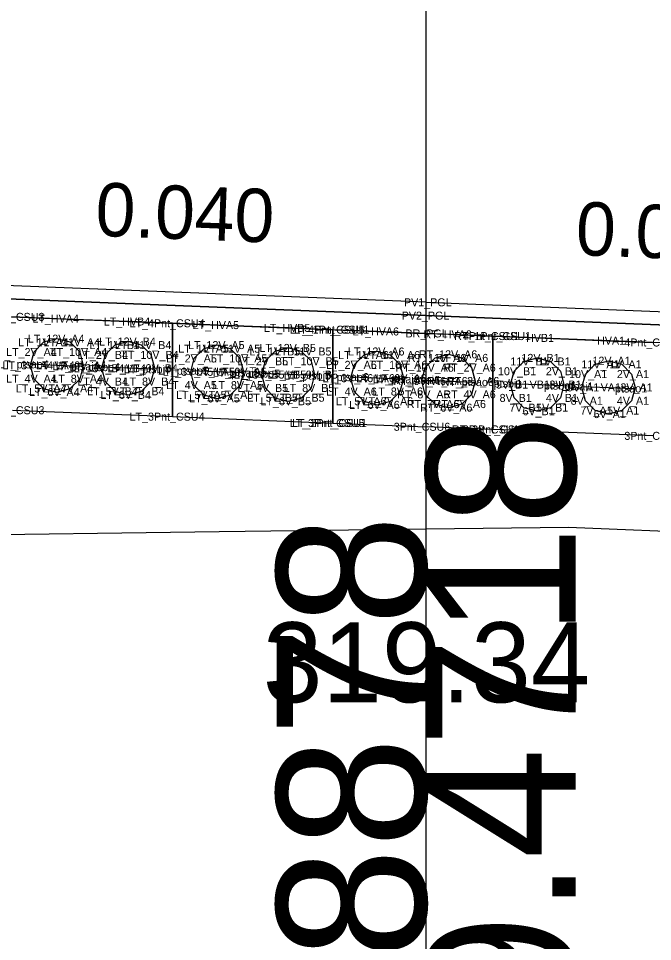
# Model space of a CAD drawing. Extents: x -26 to 1163, y -10 to 9537.
# Drawn here: x 72.36 to 84.24, y 5507.61 to 5524.91 of the extents above; entities that cross this region are included whole.
import ezdxf

# ---------------------------------------------------------------- set-up
doc = ezdxf.new("R2010")
doc.units = 0
for name, color, linetype in [('Exist Cross Section Cell', 7, 'Continuous'), ('Exist XS Center Line Elevation Label', 7, 'Continuous'), ('Exist XS Ground Line', 7, 'Continuous'), ('Prop CMT Concrete Structures', 7, 'Continuous'), ('Prop CMT Corridor Surface Symbology Blue', 7, 'Continuous'), ('Prop CMT Pvmt Course 1', 7, 'Continuous'), ('Prop CMT Pvmt Course 2', 7, 'Continuous'), ('Prop XS SE Text', 7, 'Continuous'), ('Scratch_Level_0', 7, 'Continuous')]:
    doc.layers.add(name, color=color, linetype=linetype)

msp = doc.modelspace()

# ---------------------------------------------------------------- linework, layer by layer
at = {"layer": 'Exist Cross Section Cell'}
msp.add_line((80, 5500), (80, 5546.131), dxfattribs=at)
at = {"layer": 'Exist XS Ground Line'}
msp.add_lwpolyline([(50.408, 5507.818), (57.975, 5511.563), (61.745, 5513.361), (70.287, 5515.157), (70.652, 5515.222), (76.125, 5515.292), (80, 5515.342), (82.665, 5515.377), (85.409, 5515.26), (94.805, 5514.85), (98.043, 5514.258), (104.757, 5511.598), (113.21, 5508.172), (121.817, 5507.493), (125.269, 5507.214), (127.758, 5507.11), (137.804, 5508.533), (143.24, 5508.791), (148.098, 5507.061), (150.039, 5505.923), (155.893, 5501.246), (156.599, 5500.79), (160, 5500.863)], dxfattribs=at)
at = {"layer": 'Prop CMT Concrete Structures'}
for points in [[(75.25, 5519.197), (74.417, 5519.23), (73.083, 5519.283), (72.25, 5519.317)], [(78.25, 5519.077), (77.417, 5519.11), (76.083, 5519.163), (75.25, 5519.197)], [(75.25, 5519.197), (75.25, 5517.447)], [(75.25, 5517.447), (75.25, 5519.197)], [(80, 5519.007), (79.083, 5519.043), (78.25, 5519.077)], [(78.25, 5519.077), (78.25, 5517.327)], [(78.25, 5517.327), (78.25, 5519.077)], [(73.083, 5518.908), (72.833, 5518.841), (72.65, 5518.658), (72.583, 5518.408)], [(73.583, 5518.408), (73.516, 5518.658), (73.333, 5518.841), (73.083, 5518.908)], [(74.417, 5518.855), (74.167, 5518.788), (73.984, 5518.605), (73.917, 5518.355)], [(74.917, 5518.355), (74.85, 5518.605), (74.667, 5518.788), (74.417, 5518.855)], [(80, 5517.257), (80, 5519.007)], [(80, 5519.007), (80.417, 5518.99), (81.25, 5518.957)], [(80, 5517.257), (80, 5519.007)], [(81.25, 5518.957), (81.25, 5517.207)], [(81.25, 5518.957), (82.083, 5518.923), (83.417, 5518.87), (84.25, 5518.837)], [(81.25, 5517.207), (81.25, 5518.957)], [(76.083, 5518.788), (75.833, 5518.721), (75.65, 5518.538), (75.583, 5518.288)], [(76.583, 5518.288), (76.516, 5518.538), (76.333, 5518.721), (76.083, 5518.788)], [(77.417, 5518.735), (77.167, 5518.668), (76.984, 5518.485), (76.917, 5518.235)], [(77.917, 5518.235), (77.85, 5518.485), (77.667, 5518.668), (77.417, 5518.735)], [(79.083, 5518.668), (78.833, 5518.601), (78.65, 5518.418), (78.583, 5518.168)], [(79.583, 5518.168), (79.516, 5518.418), (79.333, 5518.601), (79.083, 5518.668)], [(79.917, 5518.115), (79.984, 5518.365), (80.167, 5518.548), (80.417, 5518.615)], [(80.417, 5518.615), (80.667, 5518.548), (80.85, 5518.365), (80.917, 5518.115)], [(81.583, 5518.048), (81.65, 5518.298), (81.833, 5518.481), (82.083, 5518.548)], [(82.083, 5518.548), (82.333, 5518.481), (82.516, 5518.298), (82.583, 5518.048)], [(82.917, 5517.995), (82.984, 5518.245), (83.167, 5518.428), (83.417, 5518.495)], [(83.417, 5518.495), (83.667, 5518.428), (83.85, 5518.245), (83.917, 5517.995)], [(72.583, 5518.408), (72.65, 5518.158), (72.833, 5517.975), (73.083, 5517.908), (73.333, 5517.975), (73.516, 5518.158), (73.583, 5518.408)], [(73.917, 5518.355), (73.984, 5518.105), (74.167, 5517.922), (74.417, 5517.855), (74.667, 5517.922), (74.85, 5518.105), (74.917, 5518.355)], [(75.583, 5518.288), (75.65, 5518.038), (75.833, 5517.855), (76.083, 5517.788), (76.333, 5517.855), (76.516, 5518.038), (76.583, 5518.288)], [(76.917, 5518.235), (76.984, 5517.985), (77.167, 5517.802), (77.417, 5517.735), (77.667, 5517.802), (77.85, 5517.985), (77.917, 5518.235)], [(78.583, 5518.168), (78.65, 5517.918), (78.833, 5517.735), (79.083, 5517.668), (79.333, 5517.735), (79.516, 5517.918), (79.583, 5518.168)], [(80.917, 5518.115), (80.85, 5517.865), (80.667, 5517.682), (80.417, 5517.615), (80.167, 5517.682), (79.984, 5517.865), (79.917, 5518.115)], [(82.583, 5518.048), (82.516, 5517.798), (82.333, 5517.615), (82.083, 5517.548), (81.833, 5517.615), (81.65, 5517.798), (81.583, 5518.048)], [(83.917, 5517.995), (83.85, 5517.745), (83.667, 5517.562), (83.417, 5517.495), (83.167, 5517.562), (82.984, 5517.745), (82.917, 5517.995)], [(72.25, 5517.567), (75.25, 5517.447)], [(75.25, 5517.447), (78.25, 5517.327)], [(78.25, 5517.327), (80, 5517.257)], [(81.25, 5517.207), (80, 5517.257)], [(84.25, 5517.087), (81.25, 5517.207)]]:
    msp.add_lwpolyline(points, dxfattribs=at)
at = {"layer": 'Prop CMT Corridor Surface Symbology Blue'}
for points in [[(73.573, 5518.389), (73.083, 5518.408), (72.593, 5518.428)], [(74.907, 5518.335), (74.417, 5518.355), (73.927, 5518.375)], [(76.573, 5518.269), (76.083, 5518.288), (75.593, 5518.308)], [(77.907, 5518.215), (77.417, 5518.235), (76.927, 5518.255)], [(79.573, 5518.149), (79.083, 5518.168), (78.593, 5518.188)], [(79.927, 5518.135), (80.417, 5518.115), (80.907, 5518.095)], [(81.593, 5518.068), (82.083, 5518.048), (82.573, 5518.029)], [(82.927, 5518.015), (83.417, 5517.995), (83.907, 5517.975)]]:
    msp.add_lwpolyline(points, dxfattribs=at)
at = {"layer": 'Prop CMT Pvmt Course 1'}
for points in [[(80, 5519.59), (71, 5519.95), (61.5, 5520.33)], [(61.5, 5520.33), (61.5, 5520.08), (80, 5519.34)], [(80, 5519.34), (80, 5519.59)], [(80, 5519.59), (89, 5519.23), (98.376, 5518.855)], [(80, 5519.34), (80, 5519.59)], [(98.376, 5518.855), (98.376, 5518.605), (80, 5519.34)]]:
    msp.add_lwpolyline(points, dxfattribs=at)
at = {"layer": 'Prop CMT Pvmt Course 2'}
for points in [[(80, 5519.34), (61.5, 5520.08)], [(61.5, 5520.08), (61.5, 5519.747), (80, 5519.007)], [(80, 5519.007), (80, 5519.34)], [(80, 5519.34), (98.376, 5518.605)], [(80, 5519.007), (80, 5519.34)], [(98.376, 5518.605), (98.375, 5518.272), (80, 5519.007)]]:
    msp.add_lwpolyline(points, dxfattribs=at)

# ---------------------------------------------------------------- texts
at = {"layer": 'Exist Cross Section Cell'}
for s, p in [('E 2058789.4718', (82.8, 5490)), ('N 688802.8878', (80, 5490))]:
    msp.add_text(s, height=2.8, rotation=90, dxfattribs=at).set_placement(p)
at = {"layer": 'Exist XS Center Line Elevation Label'}
msp.add_text('319.34', height=1.5, dxfattribs=at).set_placement((76.941, 5512.092))
at = {"layer": 'Prop XS SE Text'}
for p in [(73.791, 5520.839), (82.791, 5520.479)]:
    msp.add_text('0.040', height=1, rotation=357.7094, dxfattribs=at).set_placement(p)
at = {"layer": 'Scratch_Level_0'}
for s, p in [('PV1_PGL', (79.585, 5519.515)), ('LT_4Pnt_CSU3', (71.444, 5519.242)), ('LT_HVA4', (72.625, 5519.208)), ('PV2_PGL', (79.543, 5519.265)), ('LT_HVB4', (73.961, 5519.155)), ('LT_4Pnt_CSU4', (74.444, 5519.122)), ('LT_HVA5', (75.625, 5519.088)), ('LT_HVB5', (76.961, 5519.035)), ('LT_4Pnt_CSU5', (77.444, 5519.002)), ('LT_1Pnt_CSU1', (77.53, 5519.002)), ('LT_HVA6', (78.622, 5518.968)), ('BR_PGL', (79.613, 5518.932)), ('RT_HVA6', (79.951, 5518.915)), ('RT_1Pnt_CSU1', (80.526, 5518.882)), ('4Pnt_CSU1', (80.689, 5518.882)), ('LT_1V_A4', (72.356, 5518.766)), ('LT_12V_A4', (72.539, 5518.833)), ('LT_11V_A4', (72.831, 5518.766)), ('LT_1V_B4', (73.692, 5518.713)), ('LT_12V_B4', (73.875, 5518.78)), ('LT_11V_B4', (74.167, 5518.713)), ('LT_12V_A5', (75.539, 5518.713)), ('HVB1', (81.872, 5518.848)), ('HVA1', (83.203, 5518.795)), ('4Pnt_CSU', (83.714, 5518.762)), ('LT_2V_A4', (72.131, 5518.583)), ('LT_10V_A4', (72.966, 5518.583)), ('LT_2V_B4', (73.466, 5518.53)), ('LT_10V_B4', (74.302, 5518.53)), ('LT_1V_A5', (75.356, 5518.646)), ('LT_11V_A5', (75.831, 5518.646)), ('LT_1V_B5', (76.692, 5518.593)), ('LT_12V_B5', (76.875, 5518.66)), ('LT_11V_B5', (77.167, 5518.593)), ('LT_1V_A6', (78.353, 5518.526)), ('LT_12V_A6', (78.535, 5518.593)), ('LT_11V_A6', (78.828, 5518.526)), ('RT_12V_A6', (79.865, 5518.54)), ('LT_ptsao4', (71.982, 5518.353)), ('LT_2V_A5', (75.131, 5518.463)), ('LT_10V_A5', (75.966, 5518.463)), ('LT_2V_B5', (76.466, 5518.41)), ('LT_10V_B5', (77.302, 5518.41)), ('LT_2V_A6', (78.127, 5518.343)), ('LT_10V_A6', (78.962, 5518.343)), ('RT_11V_A6', (79.658, 5518.473)), ('RT_1V_A6', (80.182, 5518.473)), ('11V_B1', (81.578, 5518.406)), ('12V_B1', (81.786, 5518.473)), ('1V_B1', (82.103, 5518.406)), ('11V_A1', (82.909, 5518.353)), ('12V_A1', (83.117, 5518.42)), ('1V_A1', (83.434, 5518.353)), ('LT_3V_A4', (72.064, 5518.333)), ('LT_VA4', (72.692, 5518.333)), ('LT_ptsai4', (73.002, 5518.314)), ('LT_9V_A4', (73.064, 5518.333)), ('LT_ptsbo4', (73.316, 5518.3)), ('LT_3V_B4', (73.399, 5518.28)), ('LT_VB4', (74.028, 5518.28)), ('LT_ptsbi4', (74.336, 5518.26)), ('LT_9V_B4', (74.399, 5518.28)), ('LT_ptsao5', (74.982, 5518.233)), ('LT_3V_A5', (75.064, 5518.213)), ('LT_VA5', (75.692, 5518.213)), ('LT_ptsai5', (76.002, 5518.194)), ('LT_9V_A5', (76.064, 5518.213)), ('LT_ptsbo5', (76.316, 5518.18)), ('RT_10V_A6', (79.426, 5518.29)), ('RT_2V_A6', (80.323, 5518.29)), ('10V_B1', (81.347, 5518.223)), ('2V_B1', (82.244, 5518.223)), ('10V_A1', (82.678, 5518.17)), ('2V_A1', (83.574, 5518.17)), ('LT_4V_A4', (72.131, 5518.083)), ('LT_8V_A4', (72.997, 5518.083)), ('LT_4V_B4', (73.466, 5518.03)), ('LT_8V_B4', (74.332, 5518.03)), ('LT_3V_B5', (76.399, 5518.16)), ('LT_VB5', (77.028, 5518.16)), ('LT_ptsbi5', (77.336, 5518.14)), ('LT_9V_B5', (77.399, 5518.16)), ('LT_ptsao6', (77.978, 5518.113)), ('LT_3V_A6', (78.06, 5518.093)), ('LT_VA6', (78.689, 5518.093)), ('LT_ptsai6', (78.998, 5518.074)), ('LT_9V_A6', (79.06, 5518.093)), ('RT_ptsai6', (79.348, 5518.06)), ('RT_9V_A6', (79.39, 5518.04)), ('RT_VA6', (80.019, 5518.04)), ('RT_ptsao6', (80.288, 5518.02)), ('RT_3V_A6', (80.39, 5518.04)), ('ptsbi1', (81.267, 5517.993)), ('LT_5V_A4', (72.314, 5517.9)), ('LT_6V_A4', (72.56, 5517.833)), ('LT_7V_A4', (72.814, 5517.9)), ('LT_5V_B4', (73.649, 5517.847)), ('LT_7V_B4', (74.149, 5517.847)), ('LT_4V_A5', (75.131, 5517.963)), ('LT_8V_A5', (75.997, 5517.963)), ('LT_4V_B5', (76.466, 5517.91)), ('LT_8V_B5', (77.332, 5517.91)), ('LT_4V_A6', (78.127, 5517.843)), ('LT_8V_A6', (78.993, 5517.843)), ('9V_B1', (81.31, 5517.973)), ('VB1', (81.939, 5517.973)), ('ptsbo1', (82.207, 5517.954)), ('3V_B1', (82.31, 5517.973)), ('ptsai1', (82.6, 5517.94)), ('9V_A1', (82.641, 5517.92)), ('VA1', (83.27, 5517.92)), ('ptsao1', (83.539, 5517.9)), ('3V_A1', (83.641, 5517.92)), ('LT_6V_B4', (73.896, 5517.78)), ('LT_5V_A5', (75.314, 5517.78)), ('LT_6V_A5', (75.56, 5517.713)), ('LT_7V_A5', (75.814, 5517.78)), ('LT_5V_B5', (76.649, 5517.727)), ('LT_6V_B5', (76.896, 5517.66)), ('LT_7V_B5', (77.149, 5517.727)), ('LT_5V_A6', (78.31, 5517.66)), ('LT_7V_A6', (78.81, 5517.66)), ('RT_8V_A6', (79.457, 5517.79)), ('RT_4V_A6', (80.323, 5517.79)), ('8V_B1', (81.377, 5517.723)), ('4V_B1', (82.244, 5517.723)), ('8V_A1', (82.708, 5517.67)), ('4V_A1', (83.574, 5517.67)), ('LT_3Pnt_CSU3', (71.444, 5517.492)), ('LT_6V_A6', (78.557, 5517.593)), ('RT_7V_A6', (79.64, 5517.607)), ('RT_6V_A6', (79.886, 5517.54)), ('RT_5V_A6', (80.14, 5517.607)), ('7V_B1', (81.56, 5517.54)), ('6V_B1', (81.807, 5517.473)), ('5V_B1', (82.06, 5517.54)), ('7V_A1', (82.891, 5517.487)), ('5V_A1', (83.391, 5517.487)), ('LT_3Pnt_CSU4', (74.444, 5517.372)), ('6V_A1', (83.138, 5517.42)), ('LT_3Pnt_CSU5', (77.444, 5517.252)), ('LT_2Pnt_CSU1', (77.487, 5517.252)), ('3Pnt_CSU6', (79.393, 5517.182)), ('RT_2Pnt_CSU1', (80.483, 5517.132)), ('3Pnt_CSU1', (80.689, 5517.132)), ('3Pnt_CSU', (83.714, 5517.012))]:
    msp.add_text(s, height=0.15, dxfattribs=at).set_placement(p)

doc.saveas('drawing.dxf')
